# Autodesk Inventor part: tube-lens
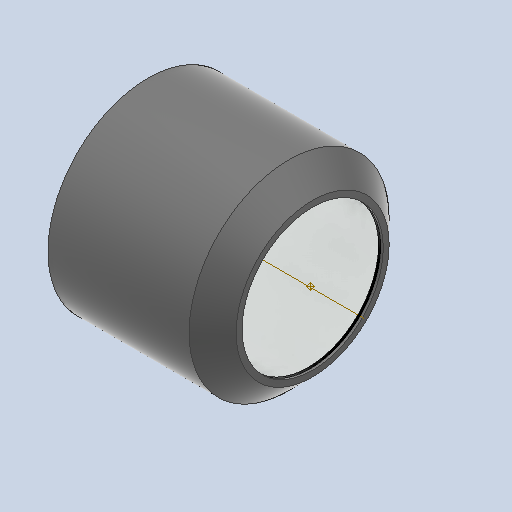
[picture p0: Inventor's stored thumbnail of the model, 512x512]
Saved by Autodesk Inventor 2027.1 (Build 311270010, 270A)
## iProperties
Created: 2026-07
Part Number: tube-lens
Material: Generic
Document SubType Name: Modeling
Designer: dunge
Density: 1 g/cm^3
Appearance: Default
Author: dunge
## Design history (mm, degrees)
sketch "Sketch1"
  geometry: L1 (0, 0)-(1.016, 0); L2 (30.48, 21.59)-(0, 21.59); L3 (0, 21.59)-(0, 0); L4 (30.48, 21.59)-(35.56, 16.51); L5 (35.56, 16.51)-(35.56, 15.24); L6 (35.56, 15.24)-(35.052, 15.24); L7 (35.052, 15.24)-(35.052, 0); L8 (35.052, 0)-(34.544, 0); L9 (0.508, 15.24)-(0.508, 0); L10 (0.508, 15.24)-(0, 15.24); L11 (1.016, 0)-(1.016, 15.24); L12 (1.016, 15.24)-(34.544, 15.24); L13 (34.544, 15.24)-(34.544, 0); 1 further point
  constraints: 26 end point, 6 perpendicular, 3 point on line, 3 vertical, 2 coincident, 2 horizontal, 2 parallel, 1 midpoint
  dimensions: "d4" = 0.508 distance of L5.end L6.end; "LIGHT_RADIUS" = 15.24 distance of L6.end L7.end; "d9" = 135 deg angle of L2 L4; "d10" = 0.508 distance of L9.start L10.end; "BODY_SIZE" = 35.56 distance between parallel lines of L3 L5; "d12" = 5.08 horizontal distance of L2.start L4.end; "d13" = 0.508 distance of L7.end L8.end; "d14" = 0.508 distance between parallel lines of L9 L11; "d18" = 21.59 distance between parallel lines of L1 L2
revolve "Revolution1" sketch "Sketch1" stored, may be unused: angle "d6" = 360 deg
workpoint "Work Point1"
  workaxis "Work Axis1"
body "Solid1"
node "Finishes"
node "Finish1" dims "Finish1_Area" = 1208.24684
node "Finish2" dims "Finish2_Area" = 291.86351
other parameters: "d15" = 0, "d16" = 0
